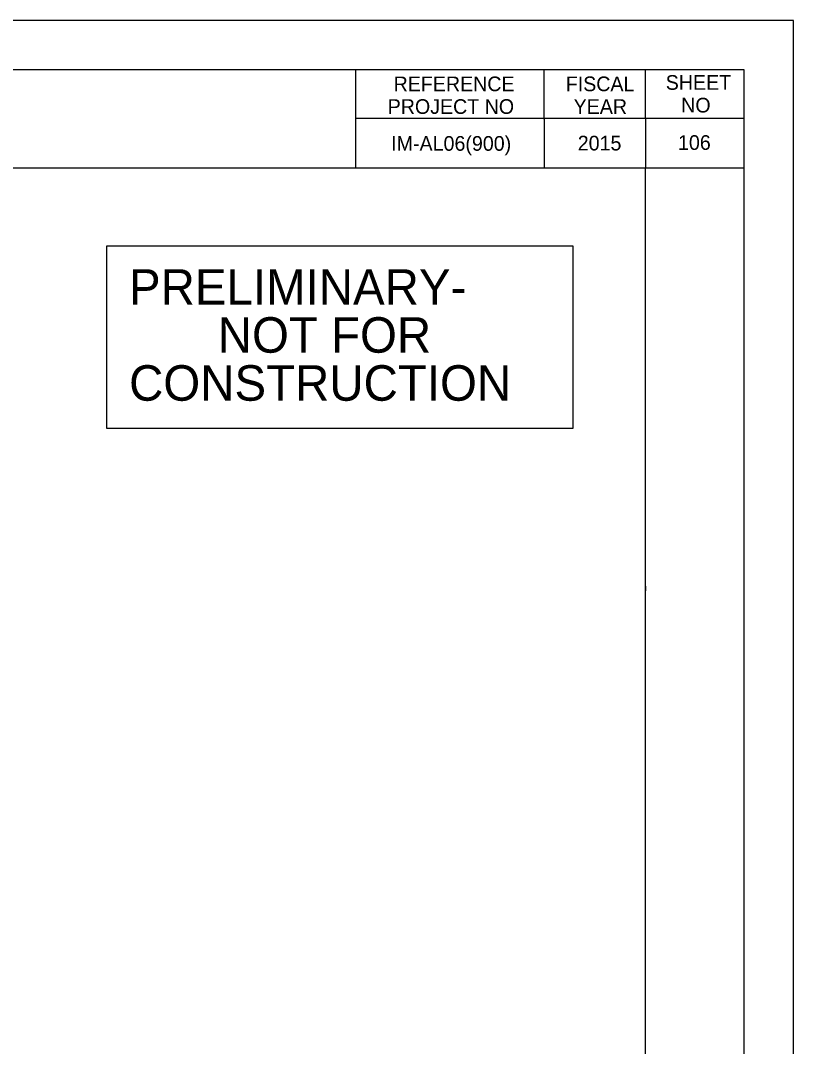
# Model space of a CAD drawing. Extents: x 515543 to 517243, y 661761 to 662861.
# Drawn here: x 516850 to 517243, y 662340 to 662861 of the extents above; entities that cross this region are included whole.
import ezdxf

# ---------------------------------------------------------------- set-up
doc = ezdxf.new("R2010")
doc.units = 0
for name, color, linetype in [('1', 7, 'Continuous'), ('2', 7, 'Continuous'), ('ANNO-SHT', 7, 'Continuous'), ('Level 6', 7, 'Continuous'), ('Level 62', 7, 'Continuous'), ('SHT-BDR', 7, 'Continuous'), ('SHT-BNDRY', 7, 'Continuous')]:
    doc.layers.add(name, color=color, linetype=linetype)

msp = doc.modelspace()

# ---------------------------------------------------------------- linework, layer by layer
at = {"layer": '1'}
msp.add_lwpolyline([(516894.14, 662746.5), (517130.56, 662746.5), (517130.56, 662653.87), (516894.14, 662653.87)], close=True, dxfattribs=at)
at = {"layer": '2'}
msp.add_lwpolyline([(517167.33, 662576.47), (517167.38, 662571.47)], dxfattribs=at)
msp.add_lwpolyline([(517167.33, 662576.47), (517167.38, 662571.47)], dxfattribs=at)
at = {"layer": 'Level 6'}
for p, q in [((517020.23, 662835.72), (517020.23, 662785.77)), ((517116.05, 662810.73), (517116.05, 662835.73)), ((517167.5, 662811.38), (517167.5, 662835.73)), ((517217.52, 662811.02), (517020.23, 662811.02)), ((517116.05, 662810.73), (517116.05, 662785.77)), ((517167.5, 662811.38), (517167.5, 662785.77)), ((517217.52, 662785.77), (517026.28, 662785.77))]:
    msp.add_line(p, q, dxfattribs=at)
at = {"layer": 'Level 62'}
msp.add_lwpolyline([(515542.51, 661760.72), (517242.52, 661760.72), (517242.52, 662860.72), (515542.51, 662860.72)], close=True, dxfattribs=at)
at = {"layer": 'SHT-BDR'}
msp.add_lwpolyline([(515667.5, 661835.77), (517167.5, 661835.77), (517167.5, 662785.77), (515667.5, 662785.77)], close=True, dxfattribs=at)
at = {"layer": 'SHT-BNDRY'}
msp.add_lwpolyline([(515605.01, 661785.72), (517217.52, 661785.72), (517217.52, 662835.72), (515605.01, 662835.72)], close=True, dxfattribs=at)

# ---------------------------------------------------------------- texts
at = {"layer": '1'}
for s, p in [('PRELIMINARY-', (516905.32, 662716.62)), ('NOT FOR', (516950.36, 662692.27)), ('CONSTRUCTION', (516905.36, 662667.92))]:
    msp.add_text(s, height=18, rotation=360, dxfattribs=at).set_placement(p)
at = {"layer": 'ANNO-SHT'}
for s, height, p in [('IM-AL06(900)', 7.4493, (517038.37, 662794.67)), ('2015', 7.449, (517133.04, 662794.83)), ('106', 7.449, (517183.91, 662795.12))]:
    msp.add_text(s, height=height, dxfattribs=at).set_placement(p)
at = {"layer": 'Level 6'}
for s, p in [('REFERENCE', (517039.6, 662824.88)), ('FISCAL', (517126.95, 662824.88)), ('SHEET', (517177.69, 662825.58)), ('PROJECT NO', (517036.6, 662813.38)), ('YEAR', (517130.95, 662813.38)), ('NO', (517185.53, 662814.08))]:
    msp.add_text(s, height=7.442, dxfattribs=at).set_placement(p)

doc.saveas('drawing.dxf')
